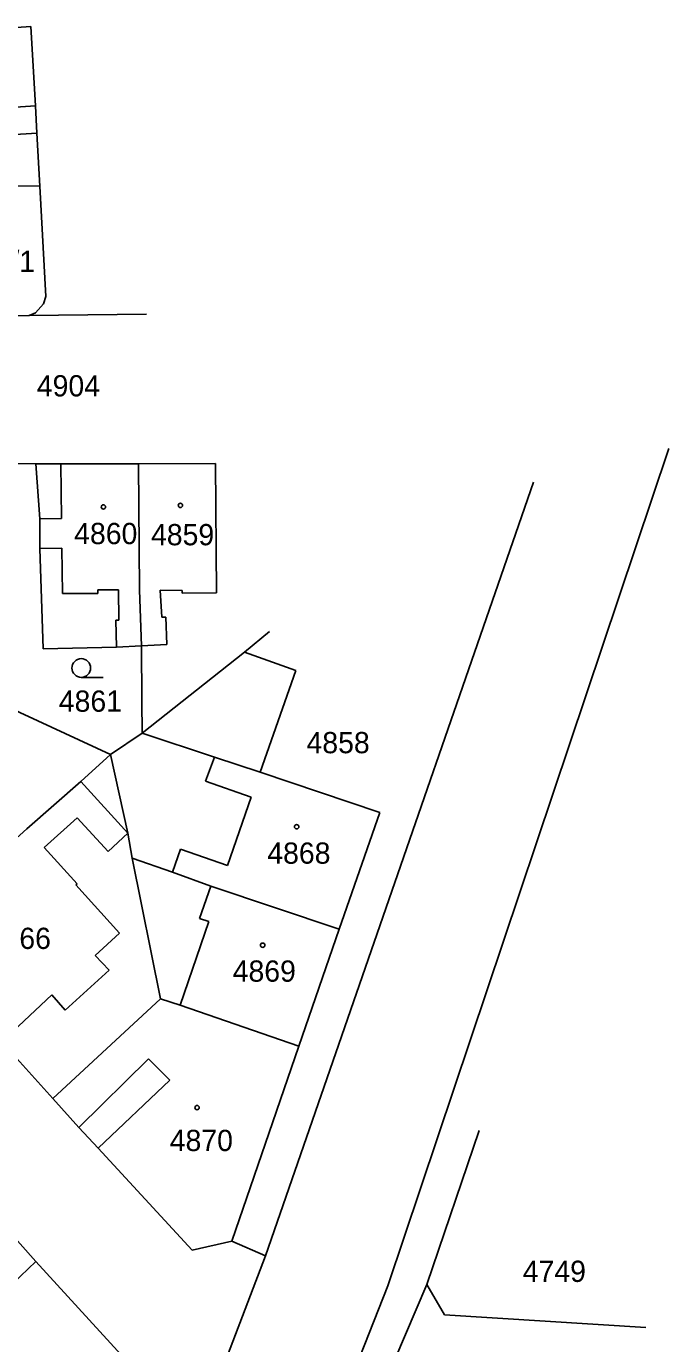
# Model space of a CAD drawing. Extents: x -735092 to -733385, y -1122435 to -1118992.
# Drawn here: x -734723.1 to -734671.7, y -1119362.8 to -1119257.4 of the extents above; entities that cross this region are included whole.
import ezdxf

# ---------------------------------------------------------------- set-up
doc = ezdxf.new("R2010")
doc.units = 0
for name, color, linetype in [('Vrstva 1', 7, 'Continuous'), ('Vrstva 18', 7, 'Continuous'), ('Vrstva 19', 7, 'Continuous'), ('Vrstva 25', 7, 'Continuous'), ('Vrstva 4', 7, 'Continuous')]:
    doc.layers.add(name, color=color, linetype=linetype)

msp = doc.modelspace()

# ---------------------------------------------------------------- linework, layer by layer
at = {"layer": 'Vrstva 1'}
for points in [[(-734732.4, -1119258.02), (-734722.74, -1119257.35)], [(-734722.74, -1119257.35), (-734722.36, -1119263.7)], [(-734722.36, -1119263.7), (-734722.26, -1119265.9)], [(-734731.37, -1119266.45), (-734722.26, -1119265.9)], [(-734722.26, -1119265.9), (-734722.02, -1119270.13)], [(-734730.96, -1119270.09), (-734722.02, -1119270.13)], [(-734722.02, -1119270.13), (-734721.52, -1119278.97)], [(-734721.71, -1119279.54), (-734721.52, -1119278.97)], [(-734730.95, -1119280.55), (-734722.87, -1119280.48)], [(-734722.87, -1119280.48), (-734722.35, -1119280.27)], [(-734722.87, -1119280.48), (-734713.48, -1119280.38)], [(-734722.35, -1119280.27), (-734721.71, -1119279.54)], [(-734694.14, -1119358.12), (-734671.67, -1119291.12)], [(-734724.72, -1119292.33), (-734722.34, -1119292.35)], [(-734722.34, -1119292.35), (-734720.34, -1119292.36)], [(-734722.34, -1119292.35), (-734722.02, -1119296.75)], [(-734720.34, -1119292.36), (-734714.11, -1119292.35)], [(-734714.11, -1119292.35), (-734707.94, -1119292.33)], [(-734714.11, -1119292.35), (-734714.02, -1119302.46)], [(-734698.31, -1119339.49), (-734682.5, -1119293.81)], [(-734722.02, -1119296.75), (-734722, -1119299.12)], [(-734722, -1119299.12), (-734721.74, -1119307.16)], [(-734714.02, -1119302.46), (-734713.87, -1119306.92)], [(-734705.62, -1119307.43), (-734703.63, -1119305.77)], [(-734721.74, -1119307.16), (-734715.87, -1119307.03)], [(-734715.87, -1119307.03), (-734713.87, -1119306.92)], [(-734713.87, -1119306.92), (-734713.84, -1119311.32)], [(-734713.83, -1119313.9), (-734705.62, -1119307.43)], [(-734705.62, -1119307.43), (-734701.51, -1119308.88)], [(-734724.71, -1119311.75), (-734716.36, -1119315.61)], [(-734713.84, -1119311.32), (-734713.83, -1119313.9)], [(-734716.36, -1119315.61), (-734713.83, -1119313.9)], [(-734713.83, -1119313.9), (-734708.03, -1119315.82)], [(-734718.74, -1119317.78), (-734716.36, -1119315.61)], [(-734716.36, -1119315.61), (-734714.96, -1119321.9)], [(-734708.03, -1119315.82), (-734704.38, -1119317.03)], [(-734704.38, -1119317.03), (-734694.8, -1119320.25)], [(-734723.04, -1119321.55), (-734718.74, -1119317.78)], [(-734698.04, -1119329.59), (-734694.8, -1119320.25)], [(-734724.99, -1119323.33), (-734723.04, -1119321.55)], [(-734714.96, -1119321.9), (-734714.62, -1119323.9)], [(-734714.62, -1119323.9), (-734712.36, -1119335.15)], [(-734714.62, -1119323.9), (-734711.38, -1119325.03)], [(-734711.38, -1119325.03), (-734708.32, -1119326.14)], [(-734708.32, -1119326.14), (-734698.04, -1119329.59)], [(-734701.27, -1119338.95), (-734698.04, -1119329.59)], [(-734720.98, -1119343.14), (-734712.36, -1119335.15)], [(-734712.36, -1119335.15), (-734710.78, -1119335.68)], [(-734710.78, -1119335.68), (-734701.27, -1119338.95)], [(-734725.06, -1119338.61), (-734720.98, -1119343.14)], [(-734706.64, -1119354.54), (-734701.27, -1119338.95)], [(-734703.94, -1119355.73), (-734698.31, -1119339.49)], [(-734720.98, -1119343.14), (-734718.88, -1119345.46)], [(-734718.88, -1119345.46), (-734717.33, -1119347.1)], [(-734691.02, -1119358.02), (-734686.85, -1119345.69)], [(-734717.33, -1119347.1), (-734709.82, -1119355.26)], [(-734728.64, -1119349.1), (-734722.32, -1119356.18)], [(-734709.82, -1119355.26), (-734706.64, -1119354.54)], [(-734706.64, -1119354.54), (-734703.94, -1119355.73)], [(-734729.71, -1119363.21), (-734722.32, -1119356.18)], [(-734722.32, -1119356.18), (-734712.94, -1119366.45)], [(-734709.39, -1119370), (-734703.94, -1119355.73)], [(-734699.37, -1119371.37), (-734694.14, -1119358.12)], [(-734696.92, -1119371.82), (-734691.02, -1119358.02)], [(-734691.02, -1119358.02), (-734689.61, -1119360.45)], [(-734689.61, -1119360.45), (-734673.51, -1119361.46)]]:
    msp.add_lwpolyline(points, dxfattribs=at)
at = {"layer": 'Vrstva 25'}
msp.add_lwpolyline([(-734718.69, -1119309.44), (-734716.94, -1119309.44)], dxfattribs=at)
for centre, radius in [((-734716.92, -1119295.8), 0.175), ((-734710.76, -1119295.68), 0.175), ((-734718.69, -1119308.69), 0.75), ((-734701.45, -1119321.39), 0.175), ((-734704.17, -1119330.87), 0.175), ((-734709.42, -1119343.86), 0.175)]:
    msp.add_circle(centre, radius, dxfattribs=at)
at = {"layer": 'Vrstva 4'}
for points in [[(-734731.94, -1119264.34), (-734722.36, -1119263.7)], [(-734720.34, -1119292.36), (-734720.28, -1119296.72)], [(-734707.94, -1119292.33), (-734707.88, -1119302.68)], [(-734722.02, -1119296.75), (-734720.28, -1119296.72)], [(-734722, -1119299.12), (-734720.25, -1119299.11)], [(-734720.25, -1119299.11), (-734720.2, -1119302.73)], [(-734717.37, -1119302.43), (-734715.72, -1119302.44)], [(-734717.37, -1119302.72), (-734717.37, -1119302.43)], [(-734715.72, -1119302.44), (-734715.69, -1119304.86)], [(-734712.38, -1119302.47), (-734712.25, -1119304.62)], [(-734712.38, -1119302.47), (-734710.62, -1119302.49)], [(-734710.62, -1119302.69), (-734710.62, -1119302.49)], [(-734720.2, -1119302.73), (-734717.37, -1119302.72)], [(-734710.62, -1119302.69), (-734707.88, -1119302.68)], [(-734712.25, -1119304.62), (-734711.92, -1119304.61)], [(-734711.92, -1119304.61), (-734711.84, -1119306.81)], [(-734715.93, -1119304.87), (-734715.69, -1119304.86)], [(-734715.93, -1119304.87), (-734715.87, -1119307.03)], [(-734713.87, -1119306.92), (-734711.84, -1119306.81)], [(-734704.38, -1119317.03), (-734701.51, -1119308.88)], [(-734708.74, -1119317.74), (-734708.03, -1119315.82)], [(-734718.74, -1119317.78), (-734714.96, -1119321.9)], [(-734708.74, -1119317.74), (-734705.08, -1119319.03)], [(-734706.98, -1119324.48), (-734705.08, -1119319.03)], [(-734721.66, -1119323.06), (-734719.03, -1119320.68)], [(-734719.03, -1119320.68), (-734716.54, -1119323.37)], [(-734716.54, -1119323.37), (-734714.96, -1119321.9)], [(-734721.66, -1119323.06), (-734719.03, -1119325.95)], [(-734711.38, -1119325.03), (-734710.75, -1119323.18)], [(-734710.75, -1119323.18), (-734706.98, -1119324.48)], [(-734719.14, -1119326.05), (-734719.03, -1119325.95)], [(-734719.14, -1119326.05), (-734715.62, -1119329.91)], [(-734709.22, -1119328.72), (-734708.32, -1119326.14)], [(-734710.78, -1119335.68), (-734708.49, -1119328.98)], [(-734709.22, -1119328.72), (-734708.49, -1119328.98)], [(-734717.58, -1119331.68), (-734715.62, -1119329.91)], [(-734717.58, -1119331.68), (-734716.46, -1119332.86)], [(-734719.99, -1119336.07), (-734716.46, -1119332.86)], [(-734725.06, -1119338.61), (-734721.06, -1119334.84)], [(-734721.06, -1119334.84), (-734719.99, -1119336.07)], [(-734718.88, -1119345.46), (-734713.31, -1119339.95)], [(-734713.31, -1119339.95), (-734711.6, -1119341.66)], [(-734717.33, -1119347.1), (-734711.6, -1119341.66)]]:
    msp.add_lwpolyline(points, dxfattribs=at)

# ---------------------------------------------------------------- texts
at = {"layer": 'Vrstva 18'}
for s, p in [('4903/1', (-734729.34, -1119277)), ('4904', (-734722.25, -1119286.96)), ('4861', (-734720.49, -1119312.19))]:
    msp.add_text(s, height=1.7, dxfattribs=at).set_placement(p)
at = {"layer": 'Vrstva 19'}
for s, p in [('4860', (-734719.26, -1119298.78)), ('4859', (-734713.11, -1119298.87)), ('4858', (-734700.66, -1119315.51)), ('4868', (-734703.8, -1119324.35)), ('4866', (-734726.18, -1119331.17)), ('4869', (-734706.57, -1119333.79)), ('4870', (-734711.61, -1119347.34)), ('4749', (-734683.35, -1119357.81))]:
    msp.add_text(s, height=1.7, dxfattribs=at).set_placement(p)

doc.saveas('drawing.dxf')
